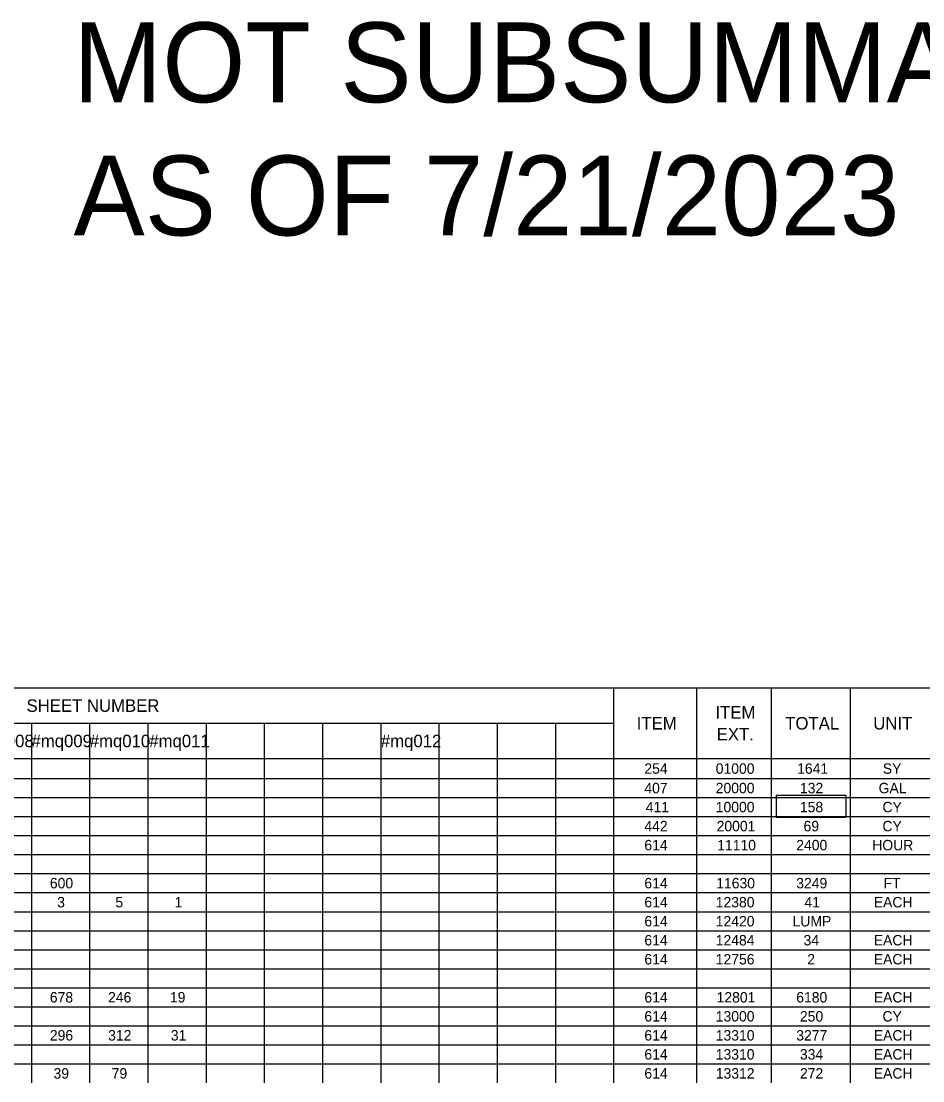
# Model space of a CAD drawing. Extents: x 91011267 to 91012802, y 37012737 to 37014266.
# Drawn here: x 91011605 to 91012252, y 37013505 to 37014266 of the extents above; entities that cross this region are included whole.
import ezdxf

# ---------------------------------------------------------------- set-up
doc = ezdxf.new("R2010")
doc.units = 0
for name, color, linetype in [('AP_P_Airside', 7, 'Continuous'), ('SC_Scratch2', 7, 'Continuous'), ('SH_Data', 7, 'Continuous')]:
    doc.layers.add(name, color=color, linetype=linetype)

msp = doc.modelspace()

# ---------------------------------------------------------------- linework, layer by layer
at = {"layer": 'AP_P_Airside'}
msp.add_lwpolyline([(91012147.08, 37013709.97), (91012196.83, 37013709.97), (91012196.83, 37013693.98), (91012147.08, 37013693.98)], close=True, dxfattribs=at)
at = {"layer": 'SC_Scratch2'}
msp.add_lwpolyline([(91011277.35, 37013787.1), (91012802.35, 37013787.1), (91012802.35, 37012737.1), (91011277.35, 37012737.1)], close=True, dxfattribs=at)
at = {"layer": 'SH_Data'}
for p, q in [((91011277.35, 37013787.1), (91011653.7, 37013787.1)), ((91011653.7, 37013787.1), (91011988.23, 37013787.1)), ((91011988.23, 37013787.1), (91012030.05, 37013787.1)), ((91012030.05, 37013787.1), (91012802.35, 37013787.1)), ((91012030.05, 37013787.1), (91012030.05, 37013708.33)), ((91012089.51, 37013787.1), (91012089.51, 37013708.33)), ((91012143.08, 37013787.1), (91012143.08, 37013708.33)), ((91012199.93, 37013787.1), (91012199.93, 37013708.33)), ((91011277.35, 37013761.71), (91011653.7, 37013761.71)), ((91011611.88, 37013761.71), (91011611.88, 37013708.33)), ((91011653.7, 37013761.71), (91011988.23, 37013761.71)), ((91011653.7, 37013761.71), (91011653.7, 37013708.33)), ((91011695.52, 37013761.71), (91011695.52, 37013708.33)), ((91011737.33, 37013761.71), (91011737.33, 37013708.33)), ((91011779.15, 37013761.71), (91011779.15, 37013708.33)), ((91011820.97, 37013761.71), (91011820.97, 37013708.33)), ((91011862.78, 37013761.71), (91011862.78, 37013708.33)), ((91011904.6, 37013761.71), (91011904.6, 37013708.33)), ((91011946.42, 37013761.71), (91011946.42, 37013708.33)), ((91011988.23, 37013761.71), (91012030.05, 37013761.71)), ((91011988.23, 37013761.71), (91011988.23, 37013708.33)), ((91011277.35, 37013736.32), (91011653.7, 37013736.32)), ((91011653.7, 37013736.32), (91011988.23, 37013736.32)), ((91011988.23, 37013736.32), (91012030.05, 37013736.32)), ((91012030.05, 37013736.32), (91012802.35, 37013736.32)), ((91011277.35, 37013722), (91011653.7, 37013722)), ((91011653.7, 37013722), (91011988.23, 37013722)), ((91011988.23, 37013722), (91012030.05, 37013722)), ((91012030.05, 37013722), (91012802.35, 37013722)), ((91011277.35, 37013708.33), (91011653.7, 37013708.33)), ((91011611.88, 37013708.33), (91011611.88, 37013694.66)), ((91011653.7, 37013708.33), (91011988.23, 37013708.33)), ((91011653.7, 37013708.33), (91011653.7, 37013694.66)), ((91011695.52, 37013708.33), (91011695.52, 37013694.66)), ((91011737.33, 37013708.33), (91011737.33, 37013694.66)), ((91011779.15, 37013708.33), (91011779.15, 37013694.66)), ((91011820.97, 37013708.33), (91011820.97, 37013694.66)), ((91011862.78, 37013708.33), (91011862.78, 37013694.66)), ((91011904.6, 37013708.33), (91011904.6, 37013694.66)), ((91011946.42, 37013708.33), (91011946.42, 37013694.66)), ((91011988.23, 37013708.33), (91012030.05, 37013708.33)), ((91011988.23, 37013708.33), (91011988.23, 37013694.66)), ((91012030.05, 37013708.33), (91012802.35, 37013708.33)), ((91012030.05, 37013708.33), (91012030.05, 37013694.66)), ((91012089.51, 37013708.33), (91012089.51, 37013694.66)), ((91012143.08, 37013708.33), (91012143.08, 37013694.66)), ((91012199.93, 37013708.33), (91012199.93, 37013694.66)), ((91011277.35, 37013694.66), (91011653.7, 37013694.66)), ((91011611.88, 37013694.66), (91011611.88, 37013626.31)), ((91011653.7, 37013694.66), (91011988.23, 37013694.66)), ((91011653.7, 37013694.66), (91011653.7, 37013626.31)), ((91011695.52, 37013694.66), (91011695.52, 37013626.31)), ((91011737.33, 37013694.66), (91011737.33, 37013626.31)), ((91011779.15, 37013694.66), (91011779.15, 37013626.31)), ((91011820.97, 37013694.66), (91011820.97, 37013626.31)), ((91011862.78, 37013694.66), (91011862.78, 37013626.31)), ((91011904.6, 37013694.66), (91011904.6, 37013626.31)), ((91011946.42, 37013694.66), (91011946.42, 37013626.31)), ((91011988.23, 37013694.66), (91012030.05, 37013694.66)), ((91011988.23, 37013694.66), (91011988.23, 37013626.31)), ((91012030.05, 37013694.66), (91012802.35, 37013694.66)), ((91012030.05, 37013694.66), (91012030.05, 37013626.31)), ((91012089.51, 37013694.66), (91012089.51, 37013626.31)), ((91012143.08, 37013694.66), (91012143.08, 37013626.31)), ((91012199.93, 37013694.66), (91012199.93, 37013626.31)), ((91011277.35, 37013680.99), (91011653.7, 37013680.99)), ((91011653.7, 37013680.99), (91011988.23, 37013680.99)), ((91011988.23, 37013680.99), (91012030.05, 37013680.99)), ((91012030.05, 37013680.99), (91012802.35, 37013680.99)), ((91011277.35, 37013667.32), (91011653.7, 37013667.32)), ((91011653.7, 37013667.32), (91011988.23, 37013667.32)), ((91011988.23, 37013667.32), (91012030.05, 37013667.32)), ((91012030.05, 37013667.32), (91012802.35, 37013667.32)), ((91011277.35, 37013653.65), (91011653.7, 37013653.65)), ((91011653.7, 37013653.65), (91011988.23, 37013653.65)), ((91011988.23, 37013653.65), (91012030.05, 37013653.65)), ((91012030.05, 37013653.65), (91012802.35, 37013653.65)), ((91011277.35, 37013639.98), (91011653.7, 37013639.98)), ((91011653.7, 37013639.98), (91011988.23, 37013639.98)), ((91011988.23, 37013639.98), (91012030.05, 37013639.98)), ((91012030.05, 37013639.98), (91012802.35, 37013639.98)), ((91011277.35, 37013626.31), (91011653.7, 37013626.31)), ((91011611.88, 37013626.31), (91011611.88, 37013612.64)), ((91011653.7, 37013626.31), (91011988.23, 37013626.31)), ((91011653.7, 37013626.31), (91011653.7, 37013612.64)), ((91011695.52, 37013626.31), (91011695.52, 37013612.64)), ((91011737.33, 37013626.31), (91011737.33, 37013612.64)), ((91011779.15, 37013626.31), (91011779.15, 37013612.64)), ((91011820.97, 37013626.31), (91011820.97, 37013612.64)), ((91011862.78, 37013626.31), (91011862.78, 37013612.64)), ((91011904.6, 37013626.31), (91011904.6, 37013612.64)), ((91011946.42, 37013626.31), (91011946.42, 37013612.64)), ((91011988.23, 37013626.31), (91012030.05, 37013626.31)), ((91011988.23, 37013626.31), (91011988.23, 37013612.64)), ((91012030.05, 37013626.31), (91012802.35, 37013626.31)), ((91012030.05, 37013626.31), (91012030.05, 37013612.64)), ((91012089.51, 37013626.31), (91012089.51, 37013612.64)), ((91012143.08, 37013626.31), (91012143.08, 37013612.64)), ((91012199.93, 37013626.31), (91012199.93, 37013612.64)), ((91011277.35, 37013612.64), (91011653.7, 37013612.64)), ((91011611.88, 37013612.64), (91011611.88, 37013598.97)), ((91011653.7, 37013612.64), (91011988.23, 37013612.64)), ((91011653.7, 37013612.64), (91011653.7, 37013598.97)), ((91011695.52, 37013612.64), (91011695.52, 37013598.97)), ((91011737.33, 37013612.64), (91011737.33, 37013598.97)), ((91011779.15, 37013612.64), (91011779.15, 37013598.97)), ((91011820.97, 37013612.64), (91011820.97, 37013598.97)), ((91011862.78, 37013612.64), (91011862.78, 37013598.97)), ((91011904.6, 37013612.64), (91011904.6, 37013598.97)), ((91011946.42, 37013612.64), (91011946.42, 37013598.97)), ((91011988.23, 37013612.64), (91012030.05, 37013612.64)), ((91011988.23, 37013612.64), (91011988.23, 37013598.97)), ((91012030.05, 37013612.64), (91012802.35, 37013612.64)), ((91012030.05, 37013612.64), (91012030.05, 37013598.97)), ((91012089.51, 37013612.64), (91012089.51, 37013598.97)), ((91012143.08, 37013612.64), (91012143.08, 37013598.97)), ((91012199.93, 37013612.64), (91012199.93, 37013598.97)), ((91011277.35, 37013598.97), (91011653.7, 37013598.97)), ((91011611.88, 37013598.97), (91011611.88, 37013503.28)), ((91011653.7, 37013598.97), (91011988.23, 37013598.97)), ((91011653.7, 37013598.97), (91011653.7, 37013503.28)), ((91011695.52, 37013598.97), (91011695.52, 37013503.28)), ((91011737.33, 37013598.97), (91011737.33, 37013503.28)), ((91011779.15, 37013598.97), (91011779.15, 37013503.28)), ((91011820.97, 37013598.97), (91011820.97, 37013503.28)), ((91011862.78, 37013598.97), (91011862.78, 37013503.28)), ((91011904.6, 37013598.97), (91011904.6, 37013503.28)), ((91011946.42, 37013598.97), (91011946.42, 37013503.28)), ((91011988.23, 37013598.97), (91012030.05, 37013598.97)), ((91011988.23, 37013598.97), (91011988.23, 37013503.28)), ((91012030.05, 37013598.97), (91012802.35, 37013598.97)), ((91012030.05, 37013598.97), (91012030.05, 37013503.28)), ((91012089.51, 37013598.97), (91012089.51, 37013503.28)), ((91012143.08, 37013598.97), (91012143.08, 37013503.28)), ((91012199.93, 37013598.97), (91012199.93, 37013503.28)), ((91011277.35, 37013585.3), (91011653.7, 37013585.3)), ((91011653.7, 37013585.3), (91011988.23, 37013585.3)), ((91011988.23, 37013585.3), (91012030.05, 37013585.3)), ((91012030.05, 37013585.3), (91012802.35, 37013585.3)), ((91011277.35, 37013571.63), (91011653.7, 37013571.63)), ((91011653.7, 37013571.63), (91011988.23, 37013571.63)), ((91011988.23, 37013571.63), (91012030.05, 37013571.63)), ((91012030.05, 37013571.63), (91012802.35, 37013571.63)), ((91011277.35, 37013557.96), (91011653.7, 37013557.96)), ((91011653.7, 37013557.96), (91011988.23, 37013557.96)), ((91011988.23, 37013557.96), (91012030.05, 37013557.96)), ((91012030.05, 37013557.96), (91012802.35, 37013557.96)), ((91011277.35, 37013544.29), (91011653.7, 37013544.29)), ((91011653.7, 37013544.29), (91011988.23, 37013544.29)), ((91011988.23, 37013544.29), (91012030.05, 37013544.29)), ((91012030.05, 37013544.29), (91012802.35, 37013544.29)), ((91011277.35, 37013530.62), (91011653.7, 37013530.62)), ((91011653.7, 37013530.62), (91011988.23, 37013530.62)), ((91011988.23, 37013530.62), (91012030.05, 37013530.62)), ((91012030.05, 37013530.62), (91012802.35, 37013530.62)), ((91011277.35, 37013516.95), (91011653.7, 37013516.95)), ((91011653.7, 37013516.95), (91011988.23, 37013516.95)), ((91011988.23, 37013516.95), (91012030.05, 37013516.95)), ((91012030.05, 37013516.95), (91012802.35, 37013516.95))]:
    msp.add_line(p, q, dxfattribs=at)

# ---------------------------------------------------------------- texts
at = {"layer": 'SC_Scratch2'}
for s, p in [('MOT SUBSUMMARY', (91011641.86, 37014208)), ('AS OF 7/21/2023', (91011642.08, 37014112.31))]:
    msp.add_text(s, height=57.4146, rotation=360, dxfattribs=at).set_placement(p)
at = {"layer": 'SH_Data'}
for s, height, p in [('SHEET NUMBER', 8.9833, (91011608.37, 37013769.91)), ('ITEM', 8.983, (91012103.16, 37013765.08)), ('ITEM', 8.983, (91012046.64, 37013757.22)), ('TOTAL', 8.983, (91012153.3, 37013757.22)), ('UNIT', 8.983, (91012216.55, 37013757.22)), ('EXT.', 8.983, (91012104.08, 37013749.36)), ('#mq008', 8.983, (91011570.12, 37013744.52)), ('#mq009', 8.983, (91011611.94, 37013744.52)), ('#mq010', 8.983, (91011653.78, 37013744.52)), ('#mq011', 8.983, (91011696.55, 37013744.52)), ('#mq012', 8.983, (91011862.87, 37013744.52)), ('254', 7.486, (91012052.13, 37013725.42)), ('01000', 7.486, (91012103.39, 37013725.42)), ('1641', 7.486, (91012161.87, 37013725.42)), ('SY', 7.486, (91012223.39, 37013725.42)), ('407', 7.486, (91012052.11, 37013711.42)), ('20000', 7.486, (91012103.39, 37013711.42)), ('132', 7.486, (91012163.88, 37013711.42)), ('GAL', 7.486, (91012220.37, 37013711.42)), ('411', 7.486, (91012053.12, 37013697.75)), ('10000', 7.486, (91012103.39, 37013697.75)), ('158', 7.486, (91012163.84, 37013697.75)), ('CY', 7.486, (91012223.13, 37013697.75)), ('442', 7.486, (91012052.15, 37013684.08)), ('20001', 7.486, (91012104.03, 37013684.08)), ('69', 7.486, (91012166.46, 37013684.08)), ('CY', 7.486, (91012223.13, 37013684.08)), ('614', 7.486, (91012052.13, 37013670.41)), ('11110', 7.486, (91012104.44, 37013670.41)), ('2400', 7.486, (91012161.23, 37013670.41)), ('HOUR', 7.486, (91012215.81, 37013670.41)), ('600', 7.486, (91011625.14, 37013643.07)), ('614', 7.486, (91012052.13, 37013643.07)), ('11630', 7.486, (91012103.74, 37013643.07)), ('3249', 7.486, (91012161.21, 37013643.07)), ('FT', 7.486, (91012223.98, 37013643.07)), ('3', 7.49, (91011630.38, 37013629.4)), ('5', 7.49, (91011672.17, 37013629.4)), ('1', 7.49, (91011714.67, 37013629.4)), ('614', 7.486, (91012052.13, 37013629.4)), ('12380', 7.486, (91012103.39, 37013629.4)), ('41', 7.486, (91012167.12, 37013629.4)), ('EACH', 7.486, (91012216.91, 37013629.4)), ('614', 7.486, (91012052.13, 37013615.73)), ('12420', 7.486, (91012103.39, 37013615.73)), ('LUMP', 7.486, (91012158.59, 37013615.73)), ('614', 7.486, (91012052.13, 37013602.06)), ('12484', 7.486, (91012103.39, 37013602.06)), ('34', 7.486, (91012166.48, 37013602.06)), ('EACH', 7.486, (91012216.91, 37013602.06)), ('614', 7.486, (91012052.13, 37013588.39)), ('12756', 7.486, (91012103.38, 37013588.39)), ('2', 7.49, (91012169.13, 37013588.39)), ('EACH', 7.486, (91012216.91, 37013588.39)), ('678', 7.486, (91011625.12, 37013561.05)), ('246', 7.486, (91011666.94, 37013561.05)), ('19', 7.486, (91011711.38, 37013561.05)), ('614', 7.486, (91012052.13, 37013561.05)), ('12801', 7.486, (91012104.03, 37013561.05)), ('6180', 7.486, (91012161.23, 37013561.05)), ('EACH', 7.486, (91012216.91, 37013561.05)), ('614', 7.486, (91012052.13, 37013547.38)), ('13000', 7.486, (91012103.39, 37013547.38)), ('250', 7.486, (91012163.86, 37013547.38)), ('CY', 7.486, (91012223.13, 37013547.38)), ('296', 7.486, (91011625.13, 37013533.71)), ('312', 7.486, (91011666.98, 37013533.71)), ('31', 7.486, (91011712.04, 37013533.71)), ('614', 7.486, (91012052.13, 37013533.71)), ('13310', 7.486, (91012103.39, 37013533.71)), ('3277', 7.486, (91012161.22, 37013533.71)), ('EACH', 7.486, (91012216.91, 37013533.71)), ('614', 7.486, (91012052.13, 37013520.04)), ('13310', 7.486, (91012103.39, 37013520.04)), ('334', 7.486, (91012163.86, 37013520.04)), ('EACH', 7.486, (91012216.91, 37013520.04)), ('39', 7.486, (91011627.75, 37013506.37)), ('79', 7.486, (91011669.56, 37013506.37)), ('614', 7.486, (91012052.13, 37013506.37)), ('13312', 7.486, (91012103.42, 37013506.37)), ('272', 7.486, (91012163.88, 37013506.37)), ('EACH', 7.486, (91012216.91, 37013506.37))]:
    msp.add_text(s, height=height, dxfattribs=at).set_placement(p)

doc.saveas('drawing.dxf')
